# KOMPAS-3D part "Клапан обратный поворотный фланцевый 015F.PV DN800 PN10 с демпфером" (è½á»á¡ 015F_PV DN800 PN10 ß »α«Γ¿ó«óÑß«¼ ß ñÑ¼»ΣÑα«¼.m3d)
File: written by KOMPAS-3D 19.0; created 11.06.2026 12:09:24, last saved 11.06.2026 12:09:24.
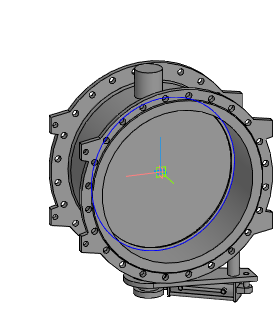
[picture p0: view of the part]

Document properties: Автор: Энергия; Полное имя файла: Z:\3.Личные\kachalov\001_3d для проектировщиков\5.5 Тип 015F.PV Клапан обратный поворотный с двумя эксцентриками\_stp_Клапан 015F.PV DN300-DN1200 с противовесом с демпфером\Клапан 015F_PV DN800 PN10 с противовесом с демпфером.m3d

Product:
- Part/product: Клапан обратный поворотный фланцевый 015F.PV DN800 PN10 с демпфером

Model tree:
1. Операция без истории:1
2. Сплайн:1
     Координата Y = 30; Координата Z = 400; Вес = 1; Координата X = 800; Координата Y = 135.322; Координата Z = 400; Вес = 0.333333; Координата X = 800; Координата Y = 135.322; Координата Z = -400; Вес = 0.333333; Координата Y = 30; Координата Z = -400; Вес = 1; Координата X = -800; Координата Y = -75.322; Координата Z = -400; Вес = 0.333333; Координата X = -800; Координата Y = -75.322; Координата Z = 400; Вес = 0.333333; Порядок = 4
